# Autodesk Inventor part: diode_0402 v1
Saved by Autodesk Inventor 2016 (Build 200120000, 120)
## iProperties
Created: 2016-09
Part Number: diode_0402 v1
Material: Generic
Document SubType Name: Modeling
Designer: Administrator
Appearance: Generic
Author: Administrator
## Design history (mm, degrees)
feature "Body6"
feature "Body8"
feature "Body19"
body "Solid1"
body "Solid2"
body "Solid3"
